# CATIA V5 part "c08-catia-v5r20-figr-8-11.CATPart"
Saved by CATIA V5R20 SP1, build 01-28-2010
Part number: Part2
Bounding box of the stored display mesh (mm): x -37.886 to 37.886, y -61.415 to 61.415, z 29 to 58
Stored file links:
  D:\v5_r20\psrt_files_downloaded\c08-catia-v5r20-prt\c08-catia-v5r20-figr-8-11.CATPart
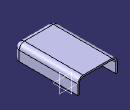
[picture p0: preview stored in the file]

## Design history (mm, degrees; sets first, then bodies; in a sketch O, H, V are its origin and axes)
Body1 (main body)
  Sketch1 on xy-plane, origin (0, 0, 0), H (1, 0, 0), V (0, 1, 0)
    line L1 (37.8862, 61.4155) -> (37.8862, -61.4155)
    line L2 (37.8862, -61.4155) -> (-37.8862, -61.4155)
    line L3 (-37.8862, -61.4155) -> (-37.8862, 61.4155)
    line L4 (-37.8862, 61.4155) -> (37.8862, 61.4155)
    vertical: L1 V, L3 V
    horizontal: L2 H, L4 H
    equidistance: L1 L3 O, L2 L4 O
  Pad1: profile Sketch1, direction (0, 0, 1), length 29
  Fillet1: radius 10, on edge [face of Pad1 | face of Pad1] (x5)
  Shell1: IntOffset 3, Face (face of Pad1; face of Pad1), ExtOffset 0
  Symmetry1: ToTransfor Shell1, Reference face of Pad1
